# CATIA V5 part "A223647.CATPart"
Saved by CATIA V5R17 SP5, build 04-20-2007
Part number: D38999_20SD19SN
Revision: -
Definition: A223647
Nomenclature: CONNECTORS, ELECTRICAL, CIRCULAR, RECEPTACLE, THREADED, WALL
Source: bought
Description: CONNECTOR, ELECTRICAL - CIRCULAR, THREADED, WALL MOUNTING FLANGE
Publications: "Logical Termination.1", "Logical Pin.1", "BCP", "Point.2_generated(BundleCnctPt1)", "Face_generated(BundleCnctPt1)", "CCP", "Point.1_generated(ConnectorCnctPt1)", "Line.4_generated(ConnectorCnctPt1)", "Line.1_generated(ConnectorCnctPt1)", "CaCP", "Point.3_generated(CavityCnctPt1)", "Line.2_generated(CavityCnctPt1)", "BaCP", "Point.4_generated(BackShellCnctPt1)", "Line.3_generated(BackShellCnctPt1)", "Face_generated(BaCP)", "Face_generated(CaCP)", "Face_generated(CCP)", "A", "B", "C", "D", "E", "F", "G", "H", "J", "K", "L", "M", "N", "P", "R", "S", "T", "U", "V"
Material "Density=.2900": density 8027.17 kg/m3
Bounding box of the stored display mesh (mm): x 0 to 33.66, y -15.5 to 15.5, z -15.5 to 15.5
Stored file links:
  C:\Users\u305772\OneDrive - Gulfstream Aerospace\AD PAG\Harness\A223647.CATPart
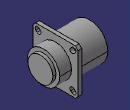
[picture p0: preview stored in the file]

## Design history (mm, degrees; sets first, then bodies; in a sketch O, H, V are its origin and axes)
Parameters
  PartNumber = "D38999_20SD19SN"
  OtherKeywords = "CONNECTORS, ELECTRICAL, CIRCULAR, RECEPTACLE, THREADED, WALL MOUNTING FLANGE, REMOVABLE CRIMP CONTACTS, SERIES III, METRIC"
  Comments = ""
  CAGECode = "81349"
  WeightComment = "SPEC"
  WeightSource = "SPEC"
  Density = 8027.17 (density)
  Volume = 1.58128e-05 (volume) {= smartVolume(Body1)}
  Shell_Length = 31.5 mm
  Max_Shell_OD = 24.95 mm
  Shell_Aft_OD = 21.974 mm
  Shell_Front_ID = 20.63 mm
  Master_Keyway_Diameter = 22.84 mm
  Master_Keyway_Width = 3.33 mm
  Flange_Width = 31 mm
  Flange_Front = 20.83 mm
  Flange_Thickness = 2.5 mm
  Flange_Diameter = 34.9 mm
  Insert_Front = 0.65 mm
  Grommet_Diameter = 16.9164 mm
  Grommet_Length = 2.16 mm
  Weight = 0.279838 {= Volume *Density *2.20462262185}
  Mounting_Holes_Inner = 23.01 mm
  Mounting_Holes_Outer = 24.61 mm
  Mounting_Holes_Diameter = 3.25 mm
AxisSystem1 "CCP": origin (0.65, 0, 0), X (1, 0, 0), Y (0, 1, 0), Z (0, 0, 1)
AxisSystem2 "CaCP": origin (20.83, 0, 0), X (1, 0, 0), Y (0, 1, 0), Z (0, 0, 1)
Set1
  Point1: (0.65 {= Insert_Front}, 0, 0)
  Point2: (33.66 {= Shell_Length+Grommet_Length}, 0, 0)
  Point3: (20.83 {= Flange_Front}, 0, 0)
  Point4: (31.5 {= Shell_Length}, 0, 0)
  Point5: (0, 0, 2.54), relative to Point1
  Point6: (0, 0, 2.54), relative to Point3
  Point7: (0, 0, 2.54), relative to Point4
  Line1: type PtPt, FirstPoint Point1, SecondPoint Point5
  Line2: type PtPt, FirstPoint Point3, SecondPoint Point6
  Line3: type PtPt, FirstPoint Point4, SecondPoint Point7
  Line4: type PtPt, FirstPoint Point1, SecondPoint Point2
Body1 "Part_Body" (main body)
  Sketch1 on yz-plane, origin (0, 0, 0), H (0, -1, 0), V (0, 0, 1)
    circle A1 centre (0, 0) radius 12.475
    point P1 (0, 0)
    radius A1 = 12.475 {= Max_Shell_OD /2}
    coincidence: P1 O
  Pad1: profile Sketch1, direction (1, 0, 0), length 20.83 {= Flange_Front}
  Sketch2 on yz-plane, origin (0, 0, 0), H (0, -1, 0), V (0, 0, 1)
    arc A1 centre (0, 0) radius 11.42 from (1.665, 11.298) to (0.5657, 11.406) ccw
    point P1 (0, 0)
    line L1 (1.665, 11.298) -> (1.665, 10.1797)
    line L2 (-1.665, 10.1797) -> (-1.665, 11.298)
    arc A2 centre (0, 0) radius 10.315 from (10.315, 0) to (1.665, 10.1797) ccw
    point P2 (0, 0)
    arc A3 centre (0, 0) radius 10.315 from (-1.665, 10.1797) to (10.315, 0) ccw
    point P3 (10.315, 0)
    point P4 (10.315, 0)
    point P5 (0.5657, 11.406)
    arc A4 centre (0, 0) radius 11.42 from (0.5657, 11.406) to (-1.665, 11.298) ccw
    point P6 (1.665, 11.298)
    point P7 (-1.665, 11.298)
    point P8 (-1.665, 10.1797)
    point P9 (1.665, 10.1797)
    radius A1 = 11.42 {= Master_Keyway_Diameter /2}
    radius A2 = 10.315 {= Shell_Front_ID /2}
    distance L2 L1 = 3.33 {= Master_Keyway_Width}
    distance P2 L2 = 1.665 {= Sketch2.distance(L2 L1)/2}
    distance P5 V = 0.5657
    coincidence: P1 O, P2 P1, A2 A3, A1 A4, P3 P4, H P3, V P1, P3 A3, P6 A4, P7 A1, P8 A2, P9 A3
    vertical: L1 V, L2 V
    perpendicularity: H L1
    concentricity: P1 A2
  Pocket1: profile Sketch2, direction (1, 0, 0), length 0.65 {= Insert_Front}
  Sketch3 on yz-plane, origin (0, 0, 0), H (0, -1, 0), V (0, 0, 1)
    line L1 (-15.5, 15.5) -> (15.5, 15.5)
    line L2 (15.5, 15.5) -> (15.5, -15.5)
    line L3 (15.5, -15.5) -> (-15.5, -15.5)
    line L4 (-15.5, -15.5) -> (-15.5, 15.5)
    distance L4 L2 = 31 {= Flange_Width}
    distance L1 L3 = 31 {= Sketch3.distance(L4 L2)}
    distance V L4 = 15.5 {= Sketch3.distance(L4 L2)/2}
    distance H L3 = 15.5 {= Sketch3.distance(V L4)}
    horizontal: L1 H, L3 H
    vertical: L2 V, L4 V
  Pad2: profile Sketch3, direction (1, 0, 0), length 23.33 {= Flange_Front+Flange_Thickness}, opposite side length -20.83 {= -Flange_Front}
  Sketch4 on yz-plane, origin (0, 0, 0), H (0, -1, 0), V (0, 0, 1)
    circle A1 centre (0, 0) radius 10.987
    point P1 (0, 0)
    radius A1 = 10.987 {= Shell_Aft_OD /2}
    coincidence: P1 O
  Pad3: profile Sketch4, direction (1, 0, 0), length 31.5 {= Shell_Length}, opposite side length -23.33 {= -Flange_Front-Flange_Thickness}
  Sketch5 on yz-plane, origin (0, 0, 0), H (0, -1, 0), V (0, 0, 1)
    circle A1 centre (0, 0) radius 8.4582
    point P1 (0, 0)
    radius A1 = 8.4582 {= Grommet_Diameter /2}
    coincidence: P1 O
  Pad4: profile Sketch5, direction (1, 0, 0), length 33.66 {= Shell_Length+Grommet_Length}, opposite side length -31.5 {= -Shell_Length}
  Sketch6 on start face of Pad2, origin (20.83, 0, 0), H (0, -1, 0), V (0, 0, 1)
    arc A1 centre (-12.305, 12.305) radius 1.625 from (-11.156, 13.454) to (-13.454, 11.156) ccw
    point P1 (-12.305, 12.305)
    arc A2 centre (-11.505, 11.505) radius 1.625 from (-12.654, 10.356) to (-10.356, 12.654) ccw
    point P2 (-11.505, 11.505)
    line L1 (-11.156, 13.454) -> (-10.356, 12.654)
    line L2 (-13.454, 11.156) -> (-12.654, 10.356)
    distance P2 V = 11.505 {= Sketch6.distance(H P2)}
    distance H P2 = 11.505 {= Mounting_Holes_Inner/2}
    distance P1 V = 12.305 {= Sketch6.distance(H P1)}
    distance H P1 = 12.305 {= Mounting_Holes_Outer/2}
    radius A2 = 1.625 {= Mounting_Holes_Diameter /2}
    radius A1 = 1.625 {= Mounting_Holes_Diameter /2}
    tangency: L1 A2, L2 A1, L2 A2, L1 A1
  Pocket2: profile Sketch6, direction (1, 0, 0), through (limit type 6)
  CircPattern1: of Pocket2, instances 4, angular step 90, axis from start face of Pad1
  Chamfer1: length 1.905, angle 45, on edge [face of Pad2 from Sketch3.L2 | face of Pad2 from Sketch3.L1]; edge [face of Pad2 from Sketch3.L3 | face of Pad2 from Sketch3.L2]; edge [face of Pad2 from Sketch3.L4 | face of Pad2 from Sketch3.L3]; edge [face of Pad2 from Sketch3.L1 | face of Pad2 from Sketch3.L4]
